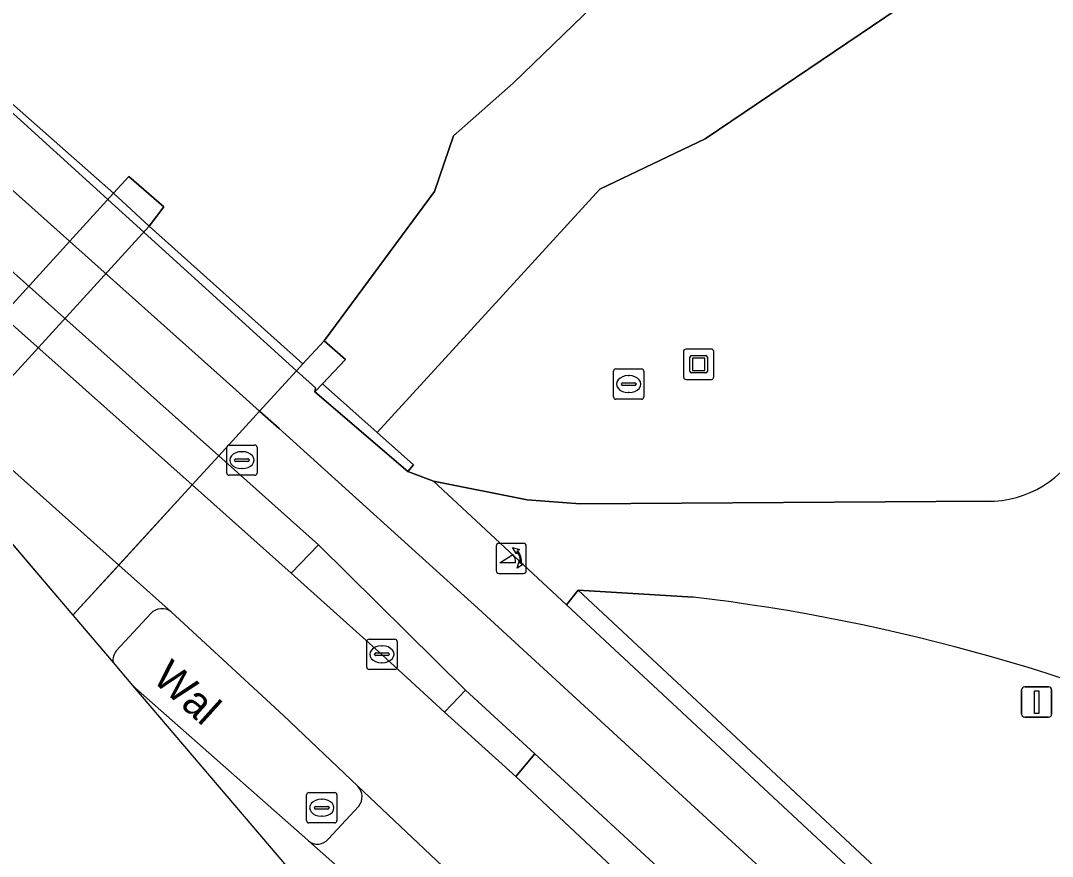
# Model space of a CAD drawing. Extents: x 161087 to 161926, y 382572 to 383873.
# Drawn here: x 161509.14 to 161543.22, y 382790.23 to 382817.85 of the extents above; entities that cross this region are included whole.
import ezdxf

# ---------------------------------------------------------------- set-up
doc = ezdxf.new("R2010")
doc.units = 0
for name, color, linetype in [('IMGEO_Berm_gesloten', 7, 'Continuous'), ('IMGEO_Berm_groen', 7, 'Continuous'), ('IMGEO_Berm_open', 7, 'Continuous'), ('IMGEO_Brandkraan', 7, 'Continuous'), ('IMGEO_Dek', 7, 'Continuous'), ('IMGEO_Fietspad_gesloten', 7, 'Continuous'), ('IMGEO_Groenvoorziening', 7, 'Continuous'), ('IMGEO_Kolk', 7, 'Continuous'), ('IMGEO_Kunstobject', 7, 'Continuous'), ('IMGEO_Lichtmast', 7, 'Continuous'), ('IMGEO_Muur', 7, 'Continuous'), ('IMGEO_Oever', 7, 'Continuous'), ('IMGEO_Openbare_ruimte_label', 7, 'Continuous'), ('IMGEO_OVBaan_gesloten', 7, 'Continuous'), ('IMGEO_Pijler', 7, 'Continuous'), ('IMGEO_Poller', 7, 'Continuous'), ('IMGEO_Rijbaan_lokaal_gesloten', 7, 'Continuous'), ('IMGEO_Rioolput', 7, 'Continuous'), ('IMGEO_Verkeerseiland_halfverhard', 7, 'Continuous'), ('IMGEO_Voetpad_gesloten', 7, 'Continuous'), ('IMGEO_Voetpad_halfverhard', 7, 'Continuous'), ('IMGEO_Voetpad_open', 7, 'Continuous'), ('IMGEO_Waterloop', 7, 'Continuous')]:
    doc.layers.add(name, color=color, linetype=linetype)

msp = doc.modelspace()

# ---------------------------------------------------------------- linework, layer by layer
at = {"layer": 'IMGEO_Berm_gesloten'}
msp.add_lwpolyline([(161510.861, 382798.2), (161512.379, 382799.859), (161500.929, 382810.086), (161500.209, 382809.289), (161505.863, 382804.066)], close=True, dxfattribs=at)
for points in [[(161514.11, 382798.313), (161512.379, 382799.859), (161510.861, 382798.2), (161512.188, 382796.642)], [(161512.303, 382797.034), (161513.438, 382798.258)]]:
    msp.add_lwpolyline(points, dxfattribs=at)
for centre, radius, start, end in [((161513.804, 382797.92), 0.498, 52.1081, 137.2498), ((161512.725, 382796.697), 0.54, 141.3974, 185.7851)]:
    msp.add_arc(centre, radius, start, end, dxfattribs=at)
at = {"layer": 'IMGEO_Berm_groen'}
msp.add_lwpolyline([(161518.974, 382800.53), (161518.074, 382799.587), (161521.077, 382796.888), (161523.137, 382795), (161523.834, 382795.731)], close=True, dxfattribs=at)
for points in [[(161526.128, 382793.617), (161525.499, 382792.875), (161529.924, 382788.722), (161532.433, 382786.262), (161534.484, 382784.238), (161538.407, 382780.287), (161541.91, 382776.676), (161545.29, 382773.157), (161547.248, 382771.146), (161548.67, 382769.538), (161549.898, 382768.125), (161550.793, 382767.071), (161551.601, 382766.003), (161552.388, 382764.975)], [(161545.714, 382775.568), (161526.128, 382793.617)]]:
    msp.add_lwpolyline(points, dxfattribs=at)
at = {"layer": 'IMGEO_Berm_open'}
for points in [[(161504.2, 382813.708), (161503.32, 382812.734), (161514.799, 382802.505), (161515.68, 382803.468)], [(161515.68, 382803.468), (161514.799, 382802.505), (161518.074, 382799.587), (161518.974, 382800.53)]]:
    msp.add_lwpolyline(points, close=True, dxfattribs=at)
at = {"layer": 'IMGEO_Brandkraan'}
for p, q in [((161515.946, 382802.9), (161515.946, 382803.752)), ((161516.021, 382803.826), (161516.873, 382803.826)), ((161516.434, 382803.606), (161516.459, 382803.606)), ((161516.947, 382803.752), (161516.947, 382802.9)), ((161516.205, 382803.32), (161516.205, 382803.332)), ((161516.643, 382803.283), (161516.245, 382803.283)), ((161516.248, 382803.369), (161516.646, 382803.369)), ((161516.689, 382803.332), (161516.689, 382803.32)), ((161516.873, 382802.826), (161516.021, 382802.826)), ((161516.457, 382803.046), (161516.432, 382803.046))]:
    msp.add_line(p, q, dxfattribs=at)
for points in [[(161515.946, 382802.9), (161515.946, 382803.752)], [(161516.021, 382803.826), (161516.873, 382803.826)], [(161516.947, 382803.752), (161516.947, 382802.9)], [(161516.873, 382802.826), (161516.021, 382802.826)]]:
    msp.add_lwpolyline(points, dxfattribs=at)
for centre, radius, start, end in [((161516.023, 382803.75), 0.0765, 91.552, 178.448), ((161516.023, 382803.75), 0.0765, 91.552, 178.448), ((161516.871, 382803.75), 0.0765, 1.552, 88.448), ((161516.871, 382803.75), 0.0765, 1.552, 88.448), ((161516.245, 382803.329), 0.0403, 85.8775, 175.7526), ((161516.242, 382803.319), 0.0366, 178.938, 274.7102), ((161516.646, 382803.326), 0.043, 264.8664, 352.4533), ((161516.65, 382803.331), 0.0386, 1.7309, 96.639), ((161516.023, 382802.902), 0.0765, 181.552, 268.448), ((161516.023, 382802.902), 0.0765, 181.552, 268.448), ((161516.871, 382802.902), 0.0765, 271.552, 358.448), ((161516.871, 382802.902), 0.0765, 271.552, 358.448)]:
    msp.add_arc(centre, radius, start, end, dxfattribs=at)
for centre, major_axis, ratio, start_param, end_param in [((161516.433, 382803.326), (-0.387, 0.002), 0.722429, 4.712389, 7.853982), ((161516.458, 382803.326), (-0.39, 0.002), 0.717154, 1.570796, 4.712389)]:
    msp.add_ellipse(centre, major_axis=major_axis, ratio=ratio, start_param=start_param, end_param=end_param, dxfattribs=at)
at = {"layer": 'IMGEO_Dek'}
msp.add_lwpolyline([(161510.861, 382798.2), (161514.799, 382802.505), (161515.68, 382803.468), (161517.032, 382804.946), (161518.253, 382806.281), (161518.457, 382806.504), (161513.385, 382811.061), (161512.201, 382812.146), (161506.961, 382816.765), (161506.84, 382816.631), (161505.549, 382815.202), (161504.2, 382813.708), (161503.32, 382812.734), (161500.209, 382809.288), (161505.863, 382804.066)], close=True, dxfattribs=at)
at = {"layer": 'IMGEO_Fietspad_gesloten'}
msp.add_lwpolyline([(161505.549, 382815.202), (161504.2, 382813.708), (161515.68, 382803.468), (161517.032, 382804.946), (161516.15, 382805.735)], close=True, dxfattribs=at)
for points in [[(161524.253, 382798.423), (161517.676, 382804.37), (161517.032, 382804.946), (161515.68, 382803.468), (161518.974, 382800.53), (161523.834, 382795.731), (161526.128, 382793.617), (161545.714, 382775.568)], [(161553.481, 382768.115), (161554.682, 382766.93), (161556.116, 382769.155), (161524.253, 382798.423)]]:
    msp.add_lwpolyline(points, dxfattribs=at)
at = {"layer": 'IMGEO_Groenvoorziening'}
for points in [[(161538.564, 382818.562), (161531.754, 382813.944), (161528.275, 382812.282), (161520.913, 382804.24), (161522.112, 382803.175), (161521.923, 382802.954), (161522.771, 382802.629), (161525.867, 382802.02), (161527.622, 382801.877), (161541.061, 382801.969)], [(161531.358, 382798.799), (161527.559, 382799.033), (161556.792, 382771.758)]]:
    msp.add_lwpolyline(points, dxfattribs=at)
for centre, radius, start, end in [((161541.104, 382805.43), 3.462, 269.2872, 333.7264), ((161524.056, 382736.696), 62.531, 64.85692, 83.29393)]:
    msp.add_arc(centre, radius, start, end, dxfattribs=at)
at = {"layer": 'IMGEO_Kolk'}
for p, q in [((161520.646, 382797.411), (161521.498, 382797.411)), ((161520.571, 382796.485), (161520.571, 382797.337)), ((161521.059, 382797.191), (161521.084, 382797.191)), ((161521.572, 382797.337), (161521.572, 382796.485)), ((161520.83, 382796.905), (161520.83, 382796.917)), ((161521.268, 382796.868), (161520.87, 382796.868)), ((161520.873, 382796.954), (161521.271, 382796.954)), ((161521.314, 382796.917), (161521.314, 382796.905)), ((161521.498, 382796.411), (161520.646, 382796.411)), ((161521.082, 382796.631), (161521.057, 382796.631))]:
    msp.add_line(p, q, dxfattribs=at)
for points in [[(161520.646, 382797.411), (161521.498, 382797.411)], [(161520.571, 382796.485), (161520.571, 382797.337)], [(161521.572, 382797.337), (161521.572, 382796.485)], [(161521.498, 382796.411), (161520.646, 382796.411)]]:
    msp.add_lwpolyline(points, dxfattribs=at)
for centre, radius, start, end in [((161520.648, 382797.335), 0.0765, 91.552, 178.448), ((161520.648, 382797.335), 0.0765, 91.552, 178.448), ((161521.496, 382797.335), 0.0765, 1.552, 88.448), ((161521.496, 382797.335), 0.0765, 1.552, 88.448), ((161520.87, 382796.914), 0.0403, 85.8775, 175.7526), ((161520.867, 382796.904), 0.0366, 178.938, 274.7102), ((161521.271, 382796.911), 0.043, 264.8664, 352.4533), ((161521.275, 382796.916), 0.0386, 1.7309, 96.639), ((161520.648, 382796.487), 0.0765, 181.552, 268.448), ((161520.648, 382796.487), 0.0765, 181.552, 268.448), ((161521.496, 382796.487), 0.0765, 271.552, 358.448), ((161521.496, 382796.487), 0.0765, 271.552, 358.448)]:
    msp.add_arc(centre, radius, start, end, dxfattribs=at)
for centre, major_axis, ratio, start_param, end_param in [((161521.058, 382796.911), (-0.387, 0.002), 0.722429, 4.712389, 7.853982), ((161521.083, 382796.911), (-0.39, 0.002), 0.717154, 1.570796, 4.712389)]:
    msp.add_ellipse(centre, major_axis=major_axis, ratio=ratio, start_param=start_param, end_param=end_param, dxfattribs=at)
at = {"layer": 'IMGEO_Kunstobject'}
for p, q in [((161531.035, 382806.909), (161531.035, 382806.068)), ((161531.035, 382806.909), (161531.035, 382806.068)), ((161531.951, 382806.993), (161531.11, 382806.993)), ((161531.951, 382806.993), (161531.11, 382806.993)), ((161532.035, 382806.077), (161532.035, 382806.918)), ((161532.035, 382806.077), (161532.035, 382806.918)), ((161531.249, 382806.257), (161531.249, 382806.731)), ((161531.299, 382806.781), (161531.773, 382806.781)), ((161531.329, 382806.681), (161531.329, 382806.307)), ((161531.723, 382806.701), (161531.349, 382806.701)), ((161531.743, 382806.307), (161531.743, 382806.681)), ((161531.823, 382806.731), (161531.823, 382806.257)), ((161531.349, 382806.287), (161531.723, 382806.287)), ((161531.119, 382805.993), (161531.96, 382805.993)), ((161531.119, 382805.993), (161531.96, 382805.993)), ((161531.773, 382806.207), (161531.299, 382806.207))]:
    msp.add_line(p, q, dxfattribs=at)
for centre, radius, start, end in [((161531.113, 382806.915), 0.0779, 92.4484, 184.2845), ((161531.113, 382806.915), 0.0779, 92.4484, 184.2845), ((161531.957, 382806.915), 0.0779, 2.4484, 94.2845), ((161531.957, 382806.915), 0.0779, 2.4484, 94.2845), ((161531.299, 382806.731), 0.05, 90, 180), ((161531.349, 382806.681), 0.02, 90, 180), ((161531.723, 382806.681), 0.02, 360, 90), ((161531.773, 382806.731), 0.05, 360, 90), ((161531.299, 382806.257), 0.05, 180, 270), ((161531.349, 382806.307), 0.02, 180, 270), ((161531.723, 382806.307), 0.02, 270, 0), ((161531.773, 382806.257), 0.05, 270, 0), ((161531.113, 382806.071), 0.0779, 182.4484, 274.2845), ((161531.113, 382806.071), 0.0779, 182.4484, 274.2845), ((161531.957, 382806.071), 0.0779, 272.4484, 4.2845), ((161531.957, 382806.071), 0.0779, 272.4484, 4.2845)]:
    msp.add_arc(centre, radius, start, end, dxfattribs=at)
at = {"layer": 'IMGEO_Lichtmast'}
for p, q in [((161542.207, 382794.932), (161542.207, 382795.732)), ((161542.207, 382795.732), (161542.207, 382794.932)), ((161542.307, 382795.832), (161543.097, 382795.832)), ((161543.097, 382795.832), (161542.307, 382795.832)), ((161543.197, 382795.732), (161543.197, 382794.932)), ((161543.197, 382794.932), (161543.197, 382795.732)), ((161543.097, 382794.832), (161542.307, 382794.832)), ((161542.307, 382794.832), (161543.097, 382794.832))]:
    msp.add_line(p, q, dxfattribs=at)
msp.add_lwpolyline([(161542.627, 382795.707), (161542.777, 382795.707), (161542.777, 382794.957), (161542.627, 382794.957), (161542.627, 382795.707)], dxfattribs=at)
for centre, start, end in [((161542.307, 382795.732), 90, 180), ((161542.307, 382795.732), 90, 180), ((161543.097, 382795.732), 0, 90), ((161543.097, 382795.732), 360, 90), ((161542.307, 382794.932), 180, 270), ((161542.307, 382794.932), 180, 270), ((161543.097, 382794.932), 270, 0), ((161543.097, 382794.932), 270, 0)]:
    msp.add_arc(centre, 0.1, start, end, dxfattribs=at)
at = {"layer": 'IMGEO_Muur'}
for points in [[(161518.253, 382806.281), (161518.457, 382806.504), (161513.385, 382811.061), (161512.201, 382812.146), (161506.961, 382816.765), (161506.84, 382816.631)], [(161519.873, 382806.655), (161519.169, 382807.271), (161518.457, 382806.504), (161518.253, 382806.281), (161518.879, 382805.714), (161518.853, 382805.583), (161519.107, 382805.843)], [(161519.107, 382805.843), (161518.853, 382805.583), (161521.923, 382802.954), (161522.112, 382803.175), (161520.913, 382804.24)]]:
    msp.add_lwpolyline(points, close=True, dxfattribs=at)
for points in [[(161527.559, 382799.033), (161527.169, 382798.541), (161556.424, 382771.318)], [(161556.792, 382771.758), (161527.559, 382799.033)]]:
    msp.add_lwpolyline(points, dxfattribs=at)
at = {"layer": 'IMGEO_Oever'}
msp.add_lwpolyline([(161567.673, 382854.998), (161561.785, 382850.004), (161551.536, 382840.839), (161546.227, 382835.938), (161545.289, 382835.072), (161543.997, 382833.828), (161538.345, 382828.385), (161531.351, 382821.543), (161525.404, 382815.787), (161523.433, 382814.044), (161522.806, 382812.198), (161519.169, 382807.271), (161519.873, 382806.655), (161519.107, 382805.843), (161520.913, 382804.24), (161528.275, 382812.282), (161531.754, 382813.944), (161538.564, 382818.562), (161541.884, 382824.196)], dxfattribs=at)
at = {"layer": 'IMGEO_OVBaan_gesloten'}
msp.add_lwpolyline([(161503.32, 382812.734), (161500.929, 382810.086), (161512.379, 382799.859), (161514.799, 382802.505)], close=True, dxfattribs=at)
msp.add_lwpolyline([(161534.484, 382784.238), (161532.433, 382786.262), (161529.924, 382788.722), (161525.499, 382792.875), (161523.137, 382795), (161521.077, 382796.888), (161518.074, 382799.587), (161514.799, 382802.505), (161512.379, 382799.859), (161514.11, 382798.313), (161517.816, 382794.889), (161520.274, 382792.552), (161523.272, 382789.723), (161527.95, 382785.101), (161533.428, 382779.592), (161533.576, 382779.443), (161541.4, 382771.448)], dxfattribs=at)
at = {"layer": 'IMGEO_Pijler'}
msp.add_lwpolyline([(161506.411, 382803.423), (161513.385, 382811.061), (161513.868, 382811.699), (161512.714, 382812.703), (161512.201, 382812.146), (161505.31, 382804.577), (161505.863, 382804.066)], close=True, dxfattribs=at)
at = {"layer": 'IMGEO_Poller'}
for p, q in [((161524.846, 382800.482), (161524.846, 382799.675)), ((161524.846, 382800.482), (161524.846, 382799.675)), ((161525.748, 382800.577), (161524.94, 382800.577)), ((161525.748, 382800.577), (161524.94, 382800.577)), ((161525.842, 382799.675), (161525.842, 382800.482)), ((161525.842, 382799.675), (161525.842, 382800.482)), ((161524.94, 382799.58), (161525.748, 382799.58)), ((161524.94, 382799.58), (161525.748, 382799.58))]:
    msp.add_line(p, q, dxfattribs=at)
for points in [[(161525.525, 382800.306), (161525.513, 382800.233), (161525.388, 382800.438)], [(161525.388, 382800.438), (161525.619, 382800.372), (161525.548, 382800.34)], [(161525.481, 382799.933), (161524.968, 382799.933), (161525.398, 382800.208)], [(161525.541, 382799.761), (161525.607, 382799.992), (161525.637, 382799.924)], [(161525.673, 382799.897), (161525.745, 382799.886), (161525.541, 382799.761)]]:
    msp.add_lwpolyline(points, dxfattribs=at)
for centre, radius, start, end in [((161524.94, 382800.482), 0.0946, 90, 180), ((161524.94, 382800.482), 0.0946, 90, 180), ((161525.748, 382800.482), 0.0946, 0, 90), ((161525.748, 382800.482), 0.0946, 0, 90), ((161525.153, 382799.983), 0.332, 351.3247, 42.4854), ((161525.167, 382799.993), 0.476, 351.7527, 41.1691), ((161525.167, 382799.993), 0.516, 349.3569, 42.2912), ((161524.94, 382799.675), 0.0946, 180, 270), ((161524.94, 382799.675), 0.0946, 180, 270), ((161525.748, 382799.675), 0.0946, 270, 0), ((161525.748, 382799.675), 0.0946, 270, 0)]:
    msp.add_arc(centre, radius, start, end, dxfattribs=at)
at = {"layer": 'IMGEO_Rijbaan_lokaal_gesloten'}
msp.add_lwpolyline([(161528.749, 382781.654), (161521.725, 382788.016), (161518.647, 382790.743), (161518.623, 382790.764), (161512.833, 382795.885), (161528.67, 382777.296)], dxfattribs=at)
at = {"layer": 'IMGEO_Rioolput'}
for p, q in [((161528.724, 382805.414), (161528.724, 382806.266)), ((161528.799, 382806.34), (161529.651, 382806.34)), ((161529.725, 382806.266), (161529.725, 382805.414)), ((161529.026, 382805.883), (161529.424, 382805.883)), ((161529.212, 382806.12), (161529.237, 382806.12)), ((161528.983, 382805.834), (161528.983, 382805.846)), ((161529.421, 382805.797), (161529.023, 382805.797)), ((161529.235, 382805.56), (161529.21, 382805.56)), ((161529.467, 382805.846), (161529.467, 382805.834)), ((161529.651, 382805.34), (161528.799, 382805.34)), ((161518.585, 382791.415), (161518.585, 382792.267)), ((161518.66, 382792.341), (161519.512, 382792.341)), ((161519.586, 382792.267), (161519.586, 382791.415)), ((161519.073, 382792.121), (161519.098, 382792.121)), ((161518.844, 382791.835), (161518.844, 382791.847)), ((161519.282, 382791.798), (161518.884, 382791.798)), ((161518.887, 382791.884), (161519.285, 382791.884)), ((161519.096, 382791.561), (161519.071, 382791.561)), ((161519.328, 382791.847), (161519.328, 382791.835)), ((161519.512, 382791.341), (161518.66, 382791.341))]:
    msp.add_line(p, q, dxfattribs=at)
for points in [[(161528.724, 382805.414), (161528.724, 382806.266)], [(161528.799, 382806.34), (161529.651, 382806.34)], [(161529.725, 382806.266), (161529.725, 382805.414)], [(161529.651, 382805.34), (161528.799, 382805.34)], [(161518.585, 382791.415), (161518.585, 382792.267)], [(161518.66, 382792.341), (161519.512, 382792.341)], [(161519.586, 382792.267), (161519.586, 382791.415)], [(161519.512, 382791.341), (161518.66, 382791.341)]]:
    msp.add_lwpolyline(points, dxfattribs=at)
for centre, radius, start, end in [((161528.801, 382806.264), 0.0765, 91.552, 178.448), ((161528.801, 382806.264), 0.0765, 91.552, 178.448), ((161529.649, 382806.264), 0.0765, 1.552, 88.448), ((161529.649, 382806.264), 0.0765, 1.552, 88.448), ((161529.023, 382805.843), 0.0403, 85.8775, 175.7526), ((161529.428, 382805.845), 0.0386, 1.7309, 96.639), ((161529.02, 382805.833), 0.0366, 178.938, 274.7102), ((161529.424, 382805.84), 0.043, 264.8664, 352.4533), ((161528.801, 382805.416), 0.0765, 181.552, 268.448), ((161528.801, 382805.416), 0.0765, 181.552, 268.448), ((161529.649, 382805.416), 0.0765, 271.552, 358.448), ((161529.649, 382805.416), 0.0765, 271.552, 358.448), ((161518.662, 382792.265), 0.0765, 91.552, 178.448), ((161518.662, 382792.265), 0.0765, 91.552, 178.448), ((161519.51, 382792.265), 0.0765, 1.552, 88.448), ((161519.51, 382792.265), 0.0765, 1.552, 88.448), ((161518.884, 382791.844), 0.0403, 85.8775, 175.7526), ((161518.881, 382791.834), 0.0366, 178.938, 274.7102), ((161519.285, 382791.841), 0.043, 264.8664, 352.4533), ((161519.289, 382791.846), 0.0386, 1.7309, 96.639), ((161518.662, 382791.417), 0.0765, 181.552, 268.448), ((161518.662, 382791.417), 0.0765, 181.552, 268.448), ((161519.51, 382791.417), 0.0765, 271.552, 358.448), ((161519.51, 382791.417), 0.0765, 271.552, 358.448)]:
    msp.add_arc(centre, radius, start, end, dxfattribs=at)
for centre, major_axis, ratio, start_param, end_param in [((161529.211, 382805.84), (-0.387, 0.002), 0.722429, 4.712389, 7.853982), ((161529.236, 382805.84), (-0.39, 0.002), 0.717154, 1.570796, 4.712389), ((161519.072, 382791.841), (-0.387, 0.002), 0.722429, 4.712389, 7.853982), ((161519.097, 382791.841), (-0.39, 0.002), 0.717154, 1.570796, 4.712389)]:
    msp.add_ellipse(centre, major_axis=major_axis, ratio=ratio, start_param=start_param, end_param=end_param, dxfattribs=at)
at = {"layer": 'IMGEO_Verkeerseiland_halfverhard'}
for points in [[(161513.438, 382798.258), (161512.303, 382797.034)], [(161520.274, 382792.552), (161517.816, 382794.889), (161514.11, 382798.313)], [(161512.188, 382796.642), (161512.833, 382795.885)], [(161512.833, 382795.885), (161518.623, 382790.764), (161518.647, 382790.743)], [(161519.293, 382790.805), (161520.306, 382791.889)]]:
    msp.add_lwpolyline(points, dxfattribs=at)
for centre, radius, start, end in [((161513.804, 382797.92), 0.498, 52.1081, 137.2498), ((161512.725, 382796.697), 0.54, 141.3974, 185.7851), ((161519.92, 382792.203), 0.497, 320.875, 44.6516), ((161518.939, 382791.096), 0.458, 230.4274, 320.5369)]:
    msp.add_arc(centre, radius, start, end, dxfattribs=at)
at = {"layer": 'IMGEO_Voetpad_gesloten'}
msp.add_lwpolyline([(161541.061, 382801.969), (161527.622, 382801.877), (161525.867, 382802.02), (161522.771, 382802.629), (161527.169, 382798.541), (161527.559, 382799.033), (161531.358, 382798.799)], dxfattribs=at)
for centre, radius, start, end in [((161541.104, 382805.43), 3.462, 269.2872, 333.7264), ((161524.056, 382736.696), 62.531, 64.85692, 83.29393)]:
    msp.add_arc(centre, radius, start, end, dxfattribs=at)
at = {"layer": 'IMGEO_Voetpad_halfverhard'}
msp.add_lwpolyline([(161523.834, 382795.731), (161523.137, 382795), (161525.499, 382792.875), (161526.128, 382793.617)], close=True, dxfattribs=at)
at = {"layer": 'IMGEO_Voetpad_open'}
msp.add_lwpolyline([(161516.15, 382805.735), (161517.032, 382804.946), (161518.253, 382806.281), (161506.84, 382816.631), (161505.549, 382815.202)], close=True, dxfattribs=at)
for points in [[(161527.169, 382798.541), (161522.771, 382802.629), (161521.923, 382802.954), (161518.853, 382805.583), (161518.879, 382805.714), (161518.253, 382806.281), (161517.032, 382804.946), (161517.676, 382804.37), (161524.253, 382798.423), (161556.116, 382769.155), (161557.477, 382770.557)], [(161556.424, 382771.318), (161527.169, 382798.541)], [(161523.272, 382789.723), (161520.274, 382792.552)], [(161520.306, 382791.889), (161519.293, 382790.805)], [(161518.647, 382790.743), (161521.725, 382788.016)]]:
    msp.add_lwpolyline(points, dxfattribs=at)
for centre, radius, start, end in [((161519.92, 382792.203), 0.497, 320.875, 44.6516), ((161518.939, 382791.096), 0.458, 230.4274, 320.5369)]:
    msp.add_arc(centre, radius, start, end, dxfattribs=at)
at = {"layer": 'IMGEO_Waterloop'}
for points in [[(161510.861, 382798.2), (161512.379, 382799.859), (161514.799, 382802.505), (161515.68, 382803.468), (161517.032, 382804.946), (161518.253, 382806.281), (161518.457, 382806.504), (161519.169, 382807.271), (161522.806, 382812.198), (161523.433, 382814.044), (161525.404, 382815.787), (161531.351, 382821.543), (161538.345, 382828.385), (161543.997, 382833.828), (161545.289, 382835.072), (161546.227, 382835.938), (161551.536, 382840.839), (161561.785, 382850.004), (161567.673, 382854.998)], [(161505.31, 382804.577), (161512.201, 382812.146), (161512.714, 382812.703), (161513.868, 382811.699), (161513.385, 382811.061), (161506.411, 382803.423), (161510.861, 382798.2)]]:
    msp.add_lwpolyline(points, dxfattribs=at)

# ---------------------------------------------------------------- texts
at = {"layer": 'IMGEO_Openbare_ruimte_label'}
msp.add_text('Wal', height=1, rotation=318.0809, dxfattribs=at).set_placement((161513.453, 382796.051))

doc.saveas('drawing.dxf')
